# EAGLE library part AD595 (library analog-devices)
ANALOG DEVICES
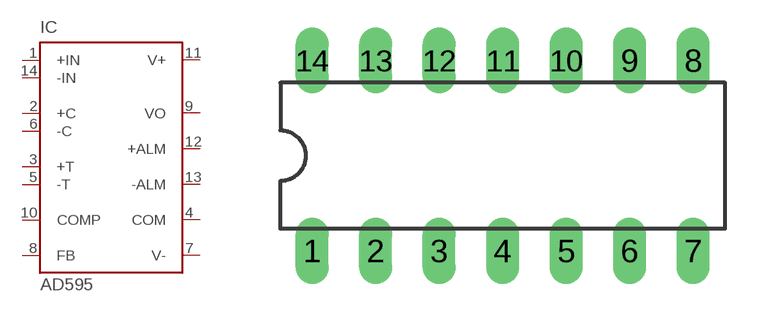
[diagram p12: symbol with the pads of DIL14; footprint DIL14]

Designator prefix IC

## AD595 (MPN: AD595AQ; OC_FARNELL: 409194; OC_NEWARK: 06WX1596)  [DIL14]
1  +IN  in
2  +C  in
3  +T  pas
4  COM  pwr
5  -T  pas
6  -C  in
7  V-  pwr
8  FB  pas
9  VO  out
10  COMP  pas
11  V+  pwr
12  +ALM  pas
13  -ALM  pas
14  -IN  in

## Footprint DIL14 (pad centres in mm)
Dual In Line Package
drill 0.813 long: 1 -7.62,-3.81; 2 -5.08,-3.81; 3 -2.54,-3.81; 4 0,-3.81; 5 2.54,-3.81; 6 5.08,-3.81; 7 7.62,-3.81; 8 7.62,3.81; 9 5.08,3.81; 10 2.54,3.81; 11 0,3.81; 12 -2.54,3.81; 13 -5.08,3.81; 14 -7.62,3.81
